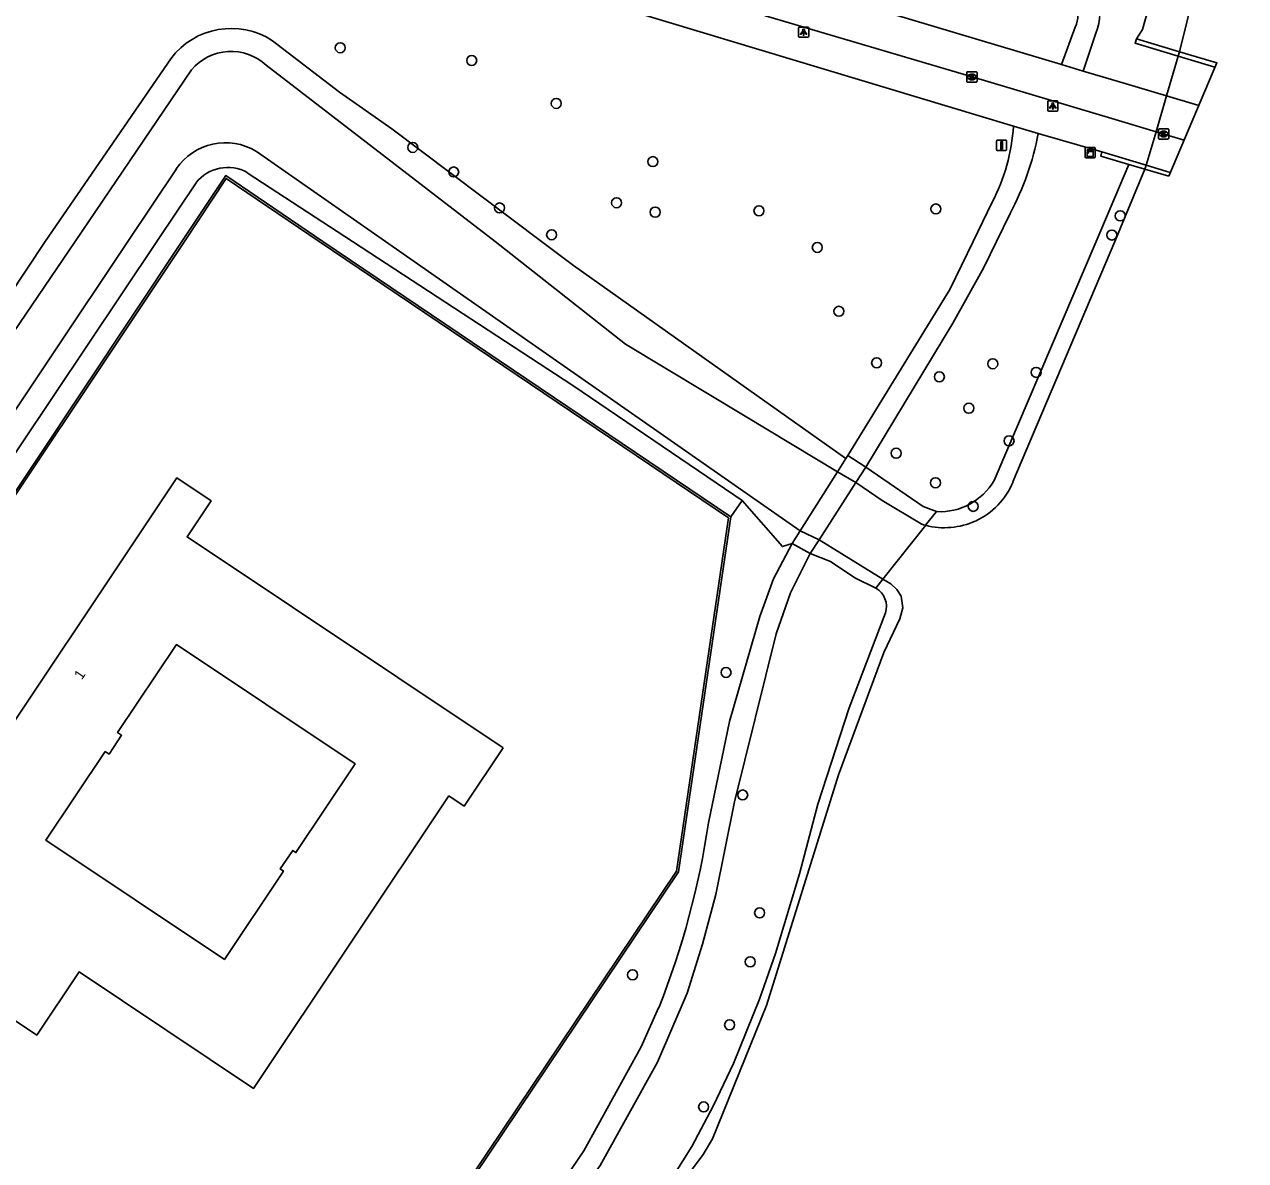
# Model space of a CAD drawing. Extents: x 160158 to 160921, y 381517 to 382041.
# Drawn here: x 160791.9 to 160911.3, y 381660.1 to 381771.2 of the extents above; entities that cross this region are included whole.
import ezdxf

# ---------------------------------------------------------------- set-up
doc = ezdxf.new("R2010")
doc.units = 0
for name, color, linetype in [('IMGEO_Berm_groen', 7, 'Continuous'), ('IMGEO_Boom', 7, 'Continuous'), ('IMGEO_Dek', 7, 'Continuous'), ('IMGEO_Fietspad_gesloten', 7, 'Continuous'), ('IMGEO_Fietspad_open', 7, 'Continuous'), ('IMGEO_Grasland_overig', 7, 'Continuous'), ('IMGEO_Groenvoorziening', 7, 'Continuous'), ('IMGEO_Kast', 7, 'Continuous'), ('IMGEO_Kolk', 7, 'Continuous'), ('IMGEO_Lichtpunt', 7, 'Continuous'), ('IMGEO_Loofbos', 7, 'Continuous'), ('IMGEO_Muur', 7, 'Continuous'), ('IMGEO_Oever', 7, 'Continuous'), ('IMGEO_Pand', 7, 'Continuous'), ('IMGEO_Pand_nummerreeks', 7, 'Continuous'), ('IMGEO_Verkeersbordpaal', 7, 'Continuous'), ('IMGEO_Voetpad_gesloten', 7, 'Continuous'), ('IMGEO_Voetpad_open', 7, 'Continuous'), ('IMGEO_Waterloop', 7, 'Continuous')]:
    doc.layers.add(name, color=color, linetype=linetype)

msp = doc.modelspace()

# ---------------------------------------------------------------- linework, layer by layer
at = {"layer": 'IMGEO_Berm_groen'}
msp.add_lwpolyline([(160904.69, 381783.05), (160901.23, 381770.74), (160900.65, 381769.8)], dxfattribs=at)
at = {"layer": 'IMGEO_Boom'}
for centre in [(160822.76, 381768.94), (160835.62, 381767.69), (160843.89, 381763.49), (160829.86, 381759.19), (160853.34, 381757.8), (160833.86, 381756.79), (160838.35, 381753.27), (160849.79, 381753.78), (160853.57, 381752.86), (160863.72, 381752.99), (160881.03, 381753.17), (160899.06, 381752.5), (160843.44, 381750.65), (160898.24, 381750.62), (160869.43, 381749.41), (160871.54, 381743.16), (160875.23, 381738.12), (160886.59, 381738.03), (160890.84, 381737.19), (160881.37, 381736.75), (160884.25, 381733.68), (160888.18, 381730.49), (160877.14, 381729.28), (160880.99, 381726.39), (160884.68, 381724.08), (160860.5, 381707.84), (160862.13, 381695.85), (160863.79, 381684.32), (160862.87, 381679.53), (160851.36, 381678.26), (160860.85, 381673.37), (160858.31, 381665.34)]:
    msp.add_circle(centre, 0.489, dxfattribs=at)
at = {"layer": 'IMGEO_Dek'}
for points in [[(160903.8, 381756.38), (160908.51, 381767.45), (160908.51, 381767.45), (160904.87, 381768.54), (160904.74, 381768.11), (160903.6, 381764.23), (160902.56, 381760.73), (160901.6, 381757.46), (160901.48, 381757.06)], [(160873.2, 381726.4), (160874.19, 381727.93), (160872.42, 381729.06), (160872.22, 381728.75), (160871.4, 381727.46), (160867.75, 381721.69), (160866.97, 381720.46), (160868.73, 381719.46), (160869.6, 381720.8)]]:
    msp.add_lwpolyline(points, close=True, dxfattribs=at)
at = {"layer": 'IMGEO_Fietspad_gesloten'}
for points in [[(160903.6, 381764.23), (160906.74, 381763.29)], [(160905.31, 381759.91), (160902.56, 381760.73)]]:
    msp.add_lwpolyline(points, dxfattribs=at)
at = {"layer": 'IMGEO_Fietspad_open'}
for points in [[(160823.24, 381789.06), (160836.93, 381784.15), (160893.31, 381767.3)], [(160820.77, 381786.23), (160825.69, 381784.41), (160838.2, 381780.05), (160845.08, 381777.86), (160864.68, 381771.96), (160884.57, 381766.08), (160898.25, 381762.01), (160902.56, 381760.73)], [(160895.43, 381766.66), (160893.31, 381767.3)], [(160903.6, 381764.23), (160899.33, 381765.5), (160895.43, 381766.66)], [(160903.6, 381764.23), (160902.56, 381760.73)]]:
    msp.add_lwpolyline(points, dxfattribs=at)
at = {"layer": 'IMGEO_Grasland_overig'}
for points in [[(160899.91, 381757.53), (160896.7, 381750), (160886.72, 381726.62)], [(160881.1, 381723.58), (160879.78, 381724.07), (160874.19, 381727.93)]]:
    msp.add_lwpolyline(points, dxfattribs=at)
msp.add_arc((160881.42, 381729.7), 6.14, 267.0172, 329.8247, dxfattribs=at)
at = {"layer": 'IMGEO_Groenvoorziening'}
for points in [[(160862.07, 381724.67), (160861.27, 381725.22), (160845.52, 381735.91), (160823.96, 381750), (160813.67, 381756.72)], [(160808.67, 381755.74), (160804.82, 381750), (160781.27, 381714.84)], [(160862.07, 381724.67), (160860.96, 381723.05)], [(160866.97, 381720.46), (160866.02, 381720.14), (160862.07, 381724.67)], [(160868.73, 381719.46), (160870.72, 381718.69), (160873.1, 381717.09), (160875.14, 381716.09)], [(160876.09, 381713.66), (160872.54, 381704.38), (160869.48, 381694.94), (160867.68, 381688.15), (160865.35, 381680.36), (160863.79, 381675.87), (160861.24, 381669.59), (160859.28, 381665.49), (160857.15, 381661.47), (160854.68, 381657.51), (160851.86, 381653.79), (160843.55, 381645.32)]]:
    msp.add_lwpolyline(points, dxfattribs=at)
for centre, radius, start, end in [((160811.75, 381753.29), 3.94, 60.7744, 141.4883), ((160874.11, 381714.29), 2.08, 342.1586, 60.1244)]:
    msp.add_arc(centre, radius, start, end, dxfattribs=at)
at = {"layer": 'IMGEO_Kast'}
for p, q in [((160895.62, 381758.26), (160895.62, 381759.1)), ((160895.62, 381759.1), (160895.62, 381758.26)), ((160895.69, 381759.18), (160896.54, 381759.18)), ((160896.54, 381759.18), (160895.69, 381759.18)), ((160896.62, 381759.11), (160896.62, 381758.27)), ((160896.62, 381758.27), (160896.62, 381759.11)), ((160896.55, 381758.18), (160895.7, 381758.18)), ((160895.7, 381758.18), (160896.55, 381758.18))]:
    msp.add_line(p, q, dxfattribs=at)
for points in [[(160895.82, 381758.97), (160896.42, 381758.97), (160896.42, 381758.89), (160895.82, 381758.89), (160895.82, 381758.97)], [(160895.82, 381758.8), (160896.42, 381758.8), (160896.42, 381758.31), (160895.82, 381758.31), (160895.82, 381758.8)]]:
    msp.add_lwpolyline(points, dxfattribs=at)
msp.add_circle((160895.9, 381758.65), 0.0377, dxfattribs=at)
for centre, start, end in [((160895.7, 381759.1), 92.4484, 184.2845), ((160895.7, 381759.1), 92.4484, 184.2845), ((160896.54, 381759.1), 2.4484, 94.2845), ((160896.54, 381759.1), 2.4484, 94.2845), ((160895.7, 381758.26), 182.4484, 274.2845), ((160895.7, 381758.26), 182.4484, 274.2845), ((160896.54, 381758.26), 272.4484, 4.2845), ((160896.54, 381758.26), 272.4484, 4.2845)]:
    msp.add_arc(centre, 0.0779, start, end, dxfattribs=at)
at = {"layer": 'IMGEO_Kolk'}
for p, q in [((160884.05, 381765.66), (160884.05, 381766.51)), ((160884.12, 381766.59), (160884.97, 381766.59)), ((160884.53, 381766.36), (160884.56, 381766.36)), ((160885.05, 381766.51), (160885.05, 381765.66)), ((160884.97, 381765.58), (160884.12, 381765.58)), ((160884.56, 381765.81), (160884.53, 381765.81)), ((160902.8, 381760.08), (160902.8, 381760.94)), ((160902.88, 381761.01), (160903.73, 381761.01)), ((160903.29, 381760.79), (160903.32, 381760.79)), ((160903.81, 381760.94), (160903.81, 381760.08)), ((160903.73, 381760.01), (160902.88, 381760.01)), ((160903.31, 381760.23), (160903.29, 381760.23))]:
    msp.add_line(p, q, dxfattribs=at)
for points in [[(160884.05, 381765.66), (160884.05, 381766.51)], [(160884.12, 381766.59), (160884.97, 381766.59)], [(160884.37, 381766.28), (160884.49, 381766.28), (160884.49, 381766.13), (160884.62, 381766.28), (160884.78, 381766.28), (160884.64, 381766.13), (160884.79, 381765.88), (160884.64, 381765.88), (160884.55, 381766.05), (160884.49, 381765.98), (160884.49, 381765.88), (160884.37, 381765.88), (160884.37, 381766.28)], [(160885.05, 381766.51), (160885.05, 381765.66)], [(160884.97, 381765.58), (160884.12, 381765.58)], [(160902.8, 381760.08), (160902.8, 381760.94)], [(160902.88, 381761.01), (160903.73, 381761.01)], [(160903.12, 381760.71), (160903.25, 381760.71), (160903.25, 381760.56), (160903.38, 381760.71), (160903.54, 381760.71), (160903.4, 381760.56), (160903.55, 381760.31), (160903.4, 381760.31), (160903.31, 381760.47), (160903.25, 381760.41), (160903.25, 381760.31), (160903.12, 381760.31), (160903.12, 381760.71)], [(160903.81, 381760.94), (160903.81, 381760.08)], [(160903.73, 381760.01), (160902.88, 381760.01)]]:
    msp.add_lwpolyline(points, dxfattribs=at)
for centre, start, end in [((160884.12, 381766.51), 91.552, 178.448), ((160884.12, 381766.51), 91.552, 178.448), ((160884.97, 381766.51), 1.552, 88.448), ((160884.97, 381766.51), 1.552, 88.448), ((160884.12, 381765.66), 181.552, 268.448), ((160884.12, 381765.66), 181.552, 268.448), ((160884.97, 381765.66), 271.552, 358.448), ((160884.97, 381765.66), 271.552, 358.448), ((160902.88, 381760.93), 91.552, 178.448), ((160902.88, 381760.93), 91.552, 178.448), ((160903.73, 381760.93), 1.552, 88.448), ((160903.73, 381760.93), 1.552, 88.448), ((160902.88, 381760.09), 181.552, 268.448), ((160902.88, 381760.09), 181.552, 268.448), ((160903.73, 381760.09), 271.552, 358.448), ((160903.73, 381760.09), 271.552, 358.448)]:
    msp.add_arc(centre, 0.0765, start, end, dxfattribs=at)
for centre, major_axis, ratio, start_param, end_param in [((160884.53, 381766.08), (-0.387, 0.002), 0.722429, 4.712389, 7.853982), ((160884.56, 381766.08), (-0.39, 0.002), 0.717154, 1.570796, 4.712389), ((160903.29, 381760.51), (-0.387, 0.002), 0.722429, 4.712389, 7.853982), ((160903.32, 381760.51), (-0.39, 0.002), 0.717154, 1.570796, 4.712389)]:
    msp.add_ellipse(centre, major_axis=major_axis, ratio=ratio, start_param=start_param, end_param=end_param, dxfattribs=at)
at = {"layer": 'IMGEO_Lichtpunt'}
for p, q in [((160867.59, 381770.86), (160867.59, 381770.06)), ((160867.59, 381770.86), (160867.59, 381770.06)), ((160868.49, 381770.96), (160867.69, 381770.96)), ((160868.49, 381770.96), (160867.69, 381770.96)), ((160867.69, 381769.96), (160868.49, 381769.96)), ((160867.69, 381769.96), (160868.49, 381769.96)), ((160868.59, 381770.06), (160868.59, 381770.86)), ((160868.59, 381770.06), (160868.59, 381770.86)), ((160891.97, 381763.64), (160891.97, 381762.84)), ((160891.97, 381763.64), (160891.97, 381762.84)), ((160892.87, 381763.74), (160892.06, 381763.74)), ((160892.87, 381763.74), (160892.06, 381763.74)), ((160892.06, 381762.74), (160892.87, 381762.74)), ((160892.06, 381762.74), (160892.87, 381762.74)), ((160892.96, 381762.84), (160892.96, 381763.64)), ((160892.96, 381762.84), (160892.96, 381763.64))]:
    msp.add_line(p, q, dxfattribs=at)
for points in [[(160867.97, 381770.53), (160868, 381770.5), (160867.82, 381770.24), (160867.78, 381770.26), (160867.97, 381770.53)], [(160868.07, 381770.48), (160868.11, 381770.48), (160868.11, 381770.16), (160868.07, 381770.16), (160868.07, 381770.48)], [(160868.18, 381770.5), (160868.22, 381770.53), (160868.4, 381770.26), (160868.36, 381770.24), (160868.18, 381770.5)], [(160892.34, 381763.31), (160892.38, 381763.28), (160892.19, 381763.02), (160892.15, 381763.05), (160892.34, 381763.31)], [(160892.44, 381763.26), (160892.49, 381763.26), (160892.49, 381762.94), (160892.44, 381762.94), (160892.44, 381763.26)], [(160892.55, 381763.28), (160892.59, 381763.31), (160892.78, 381763.04), (160892.74, 381763.02), (160892.55, 381763.28)]]:
    msp.add_lwpolyline(points, dxfattribs=at)
for centre in [(160868.09, 381770.66), (160892.47, 381763.44)]:
    msp.add_circle(centre, 0.0994, dxfattribs=at)
for centre, start, end in [((160867.69, 381770.86), 90, 180), ((160867.69, 381770.86), 90, 180), ((160867.69, 381770.06), 180, 270), ((160867.69, 381770.06), 180, 270), ((160868.49, 381770.86), 0, 90), ((160868.49, 381770.86), 0, 90), ((160868.49, 381770.06), 270, 0), ((160868.49, 381770.06), 270, 360), ((160892.06, 381763.64), 90, 180), ((160892.06, 381763.64), 90, 180), ((160892.06, 381762.84), 180, 270), ((160892.06, 381762.84), 180, 270), ((160892.87, 381763.64), 0, 90), ((160892.87, 381763.64), 0, 90), ((160892.87, 381762.84), 270, 0), ((160892.87, 381762.84), 270, 360)]:
    msp.add_arc(centre, 0.0946, start, end, dxfattribs=at)
at = {"layer": 'IMGEO_Loofbos'}
for points in [[(160872.42, 381729.06), (160872.22, 381728.75), (160862.73, 381735.48), (160845.57, 381747.65), (160842.45, 381750), (160827.8, 381761.01), (160822.7, 381764.59), (160816.13, 381769.62)], [(160806.2, 381767.87), (160793.89, 381750), (160774.15, 381720.21)]]:
    msp.add_lwpolyline(points, dxfattribs=at)
msp.add_arc((160812.1, 381763.47), 7.36, 56.7615, 143.3065, dxfattribs=at)
at = {"layer": 'IMGEO_Muur'}
for points in [[(160904.74, 381768.11), (160900.52, 381769.38), (160900.65, 381769.8)], [(160900.65, 381769.8), (160904.87, 381768.54)], [(160904.87, 381768.54), (160904.74, 381768.11)], [(160908.33, 381767.03), (160904.74, 381768.11)], [(160899.91, 381757.53), (160897.17, 381758.34), (160897.25, 381758.77)], [(160897.25, 381758.77), (160901.6, 381757.46)], [(160901.48, 381757.06), (160899.91, 381757.53)], [(160901.6, 381757.46), (160901.48, 381757.06)], [(160901.6, 381757.46), (160903.96, 381756.75)], [(160780.66, 381709.64), (160746.07, 381658.25), (160790.57, 381616.68), (160820.21, 381635.63), (160855.65, 381688.4), (160860.74, 381722.95), (160820.71, 381750), (160811.61, 381756.15), (160807.52, 381750), (160783.35, 381713.75)], [(160783.19, 381713.86), (160807.28, 381750), (160811.56, 381756.43), (160821.07, 381750), (160860.96, 381723.05)], [(160860.96, 381723.05), (160855.84, 381688.32), (160820.35, 381635.48), (160790.55, 381616.43)]]:
    msp.add_lwpolyline(points, dxfattribs=at)
at = {"layer": 'IMGEO_Oever'}
for points in [[(160880.02, 381722.23), (160881.1, 381723.58)], [(160875.84, 381716.97), (160875.14, 381716.09)]]:
    msp.add_lwpolyline(points, dxfattribs=at)
at = {"layer": 'IMGEO_Pand'}
for points in [[(160838.71, 381700.46), (160834.9, 381694.76), (160833.4, 381695.76), (160814.29, 381667.15), (160797.21, 381678.55), (160793.08, 381672.36), (160782.77, 381679.24), (160786.86, 381685.37), (160778.89, 381690.69), (160780.07, 381692.46), (160777.63, 381694.09), (160779.06, 381696.23), (160781.46, 381694.63), (160782.65, 381696.41), (160785.26, 381694.66), (160806.77, 381726.87), (160810.13, 381724.62), (160807.78, 381721.1), (160838.71, 381700.46)], [(160799.77, 381700.11), (160800.15, 381699.85), (160801.38, 381701.69), (160800.98, 381701.95), (160806.73, 381710.56), (160824.21, 381698.89), (160818.42, 381690.21), (160818.11, 381690.42), (160816.9, 381688.61), (160817.21, 381688.4), (160811.44, 381679.76), (160793.97, 381691.42), (160799.77, 381700.11)]]:
    msp.add_lwpolyline(points, dxfattribs=at)
at = {"layer": 'IMGEO_Verkeersbordpaal'}
for p, q in [((160886.96, 381759), (160886.96, 381759.8)), ((160886.96, 381759.8), (160886.96, 381759)), ((160887.06, 381759.9), (160887.85, 381759.9)), ((160887.85, 381759.9), (160887.06, 381759.9)), ((160887.95, 381759.8), (160887.95, 381759)), ((160887.95, 381759), (160887.95, 381759.8)), ((160887.85, 381758.9), (160887.06, 381758.9)), ((160887.06, 381758.9), (160887.85, 381758.9))]:
    msp.add_line(p, q, dxfattribs=at)
msp.add_lwpolyline([(160887.38, 381759.77), (160887.53, 381759.77), (160887.53, 381759.02), (160887.38, 381759.02), (160887.38, 381759.77)], dxfattribs=at)
for centre, start, end in [((160887.06, 381759.8), 90, 180), ((160887.06, 381759.8), 90, 180), ((160887.85, 381759.8), 0, 90), ((160887.85, 381759.8), 360, 90), ((160887.06, 381759), 180, 270), ((160887.06, 381759), 180, 270), ((160887.85, 381759), 270, 0), ((160887.85, 381759), 270, 0)]:
    msp.add_arc(centre, 0.1, start, end, dxfattribs=at)
at = {"layer": 'IMGEO_Voetpad_gesloten'}
for points in [[(160891.04, 381760.56), (160888.61, 381761.28)], [(160872.42, 381729.06), (160882.38, 381745.29), (160884.67, 381750), (160886.53, 381753.82)], [(160888.28, 381752.71), (160886.96, 381750), (160885.71, 381747.43), (160882.69, 381742), (160874.19, 381727.93)], [(160873.2, 381726.4), (160874.19, 381727.93), (160872.42, 381729.06), (160872.22, 381728.75), (160871.4, 381727.46), (160867.75, 381721.69), (160866.97, 381720.46), (160868.73, 381719.46), (160869.6, 381720.8), (160873.2, 381726.4)], [(160874.19, 381727.93), (160872.42, 381729.06)], [(160858.78, 381693.12), (160860.83, 381703.04), (160863.81, 381713.3), (160865.13, 381716.99), (160866.97, 381720.46)], [(160866.97, 381720.46), (160868.73, 381719.46)], [(160868.73, 381719.46), (160866.82, 381715.63), (160865.41, 381711.6), (160861.34, 381695.19), (160859.49, 381686.11), (160858.2, 381681.25), (160856.69, 381676.45), (160853.81, 381669.7), (160848.2, 381659.61), (160842.12, 381651.05), (160838.4, 381646.23)], [(160791.95, 381613.46), (160793.53, 381614), (160806.92, 381622.08), (160812.28, 381625.56), (160815.77, 381628.23), (160833.62, 381644.48), (160837.29, 381648.09), (160840.52, 381652.1), (160846.58, 381661.03), (160852.21, 381671.21), (160853.91, 381675.02)]]:
    msp.add_lwpolyline(points, dxfattribs=at)
for centre, radius, start, end in [((160870.48, 381762.31), 18.16, 332.1383, 356.7516), ((160863.94, 381765.69), 27.58, 331.9381, 349.2835), ((160778.3, 381705.04), 81.36, 338.3447, 351.5735)]:
    msp.add_arc(centre, radius, start, end, dxfattribs=at)
at = {"layer": 'IMGEO_Voetpad_open'}
for points in [[(160888.61, 381761.28), (160839.44, 381776.11), (160820.7, 381782.66), (160805.66, 381788.42), (160801.4, 381790.42)], [(160893.31, 381767.3), (160894.66, 381770.94)], [(160896.67, 381770.38), (160895.43, 381766.66)], [(160897.25, 381758.77), (160891.04, 381760.56)], [(160902.56, 381760.73), (160901.6, 381757.46)]]:
    msp.add_lwpolyline(points, dxfattribs=at)
for centre, radius, start, end in [((160891.71, 381772.44), 5.37, 337.4293, 57.4885), ((160891.38, 381772.3), 3.55, 337.4849, 55.8989)]:
    msp.add_arc(centre, radius, start, end, dxfattribs=at)
at = {"layer": 'IMGEO_Waterloop'}
for points in [[(160911.32, 381792.4), (160906.31, 381774.51), (160904.87, 381768.54)], [(160904.74, 381768.11), (160903.6, 381764.23)], [(160775.76, 381719), (160796.82, 381750), (160808.22, 381766.79)], [(160815.52, 381767.23), (160837.93, 381750), (160850.68, 381739.95), (160862.36, 381732.91), (160871.4, 381727.46), (160873.2, 381726.4), (160875.76, 381724.65), (160879.58, 381722.36), (160879.8, 381722.29), (160880.02, 381722.23)], [(160814.56, 381758.8), (160827.18, 381750), (160861.4, 381726.12), (160867.75, 381721.69), (160869.6, 381720.8), (160875.84, 381716.97)], [(160779.43, 381716.23), (160801.99, 381750), (160806.73, 381757.1)], [(160901.48, 381757.06), (160898.54, 381750), (160888.57, 381726.47)], [(160880.03, 381722.23), (160875.85, 381716.96)], [(160880.02, 381722.23), (160880.03, 381722.23)], [(160875.85, 381716.96), (160876.61, 381716.5), (160877.2, 381715.96), (160877.63, 381715.3), (160877.78, 381714.17), (160877.51, 381713.07), (160875.93, 381709.79), (160871.51, 381697.83), (160864.45, 381675.26), (160859.19, 381662.23), (160858.26, 381660.7), (160854.41, 381655.52), (160847.44, 381647), (160830.52, 381630.47), (160824.35, 381624.7), (160818.68, 381619.39), (160812.69, 381614.8), (160800.26, 381605.88)], [(160875.85, 381716.96), (160875.84, 381716.97)]]:
    msp.add_lwpolyline(points, dxfattribs=at)
for centre, radius, start, end in [((160812.08, 381763.55), 5.03, 46.8692, 140.0303), ((160811.53, 381753.85), 5.8, 58.5511, 145.945), ((160881.88, 381729.23), 7.24, 294.5608, 337.5901), ((160881.87, 381729.23), 7.24, 255.3183, 294.5997)]:
    msp.add_arc(centre, radius, start, end, dxfattribs=at)

# ---------------------------------------------------------------- texts
at = {"layer": 'IMGEO_Pand_nummerreeks'}
msp.add_text('1', height=1, rotation=56.2722, dxfattribs=at).set_placement((160797.48, 381707.05))

doc.saveas('drawing.dxf')
